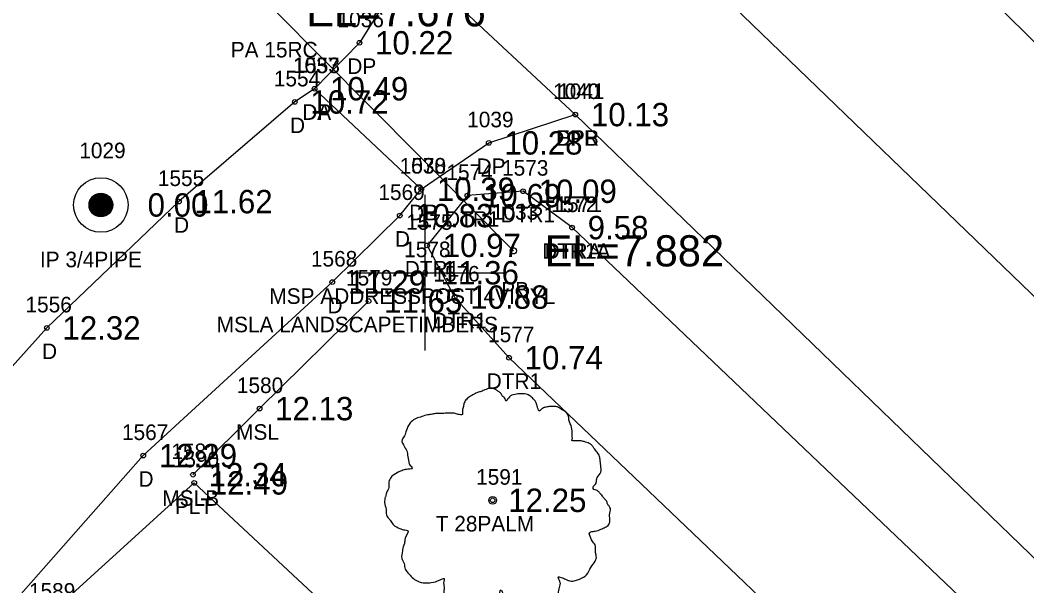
# Model space of a CAD drawing. Extents: x 2608598 to 2610682, y 641451 to 643526.
# Drawn here: x 2608785.1 to 2608849.7, y 643321 to 643357.3 of the extents above; entities that cross this region are included whole.
import ezdxf

# ---------------------------------------------------------------- set-up
doc = ezdxf.new("R2010")
doc.units = 0
for name, color, linetype in [('RD_EX_BldgApp', 7, 'Continuous'), ('RD_EX_BldgApp_txCode', 7, 'Continuous'), ('RD_EX_DR_Pipe', 7, 'Continuous'), ('RD_EX_DR_Pipe_txCode', 7, 'Continuous'), ('RD_EX_Driveway', 7, 'Continuous'), ('RD_EX_Driveway_txCode', 7, 'Continuous'), ('RD_EX_DV_Prop_txCode', 7, 'Continuous'), ('RD_EX_DV_PropPin', 7, 'Continuous'), ('RD_EX_H2O', 7, 'Continuous'), ('RD_EX_H2O_txCode', 7, 'Continuous'), ('RD_EX_Misc', 7, 'Continuous'), ('RD_EX_Misc_txCode', 7, 'Continuous'), ('RD_EX_Road', 7, 'Continuous'), ('RD_EX_Road_txCode', 7, 'Continuous'), ('RD_EX_TX_BldgApp_ELEV', 7, 'Continuous'), ('RD_EX_TX_Driveway_ELEV', 7, 'Continuous'), ('RD_EX_TX_DV_Prop_ELEV', 7, 'Continuous'), ('RD_EX_TX_H2O_ELEV', 7, 'Continuous'), ('RD_EX_TX_Misc_ELEV', 7, 'Continuous'), ('RD_EX_TX_Road_ELEV', 7, 'Continuous'), ('RD_EX_TX_VEG_ELEV', 7, 'Continuous'), ('RD_EX_VEG', 7, 'Continuous'), ('RD_EX_VEG_txCode', 7, 'Continuous'), ('RD_HC_Cl', 7, 'Continuous'), ('RD_SMD_Locator', 7, 'Continuous'), ('RD_TX_Pipe_ElevEX', 7, 'Continuous')]:
    doc.layers.add(name, color=color, linetype=linetype)

msp = doc.modelspace()

# ---------------------------------------------------------------- linework, layer by layer
at = {"layer": 'RD_EX_BldgApp'}
msp.add_lwpolyline([(2608782.007, 643313.14), (2608787.031, 643319.174), (2608796.295, 643327.605), (2608820.69, 643304.856), (2608835.733, 643299.436), (2608852.861, 643282.476), (2608829.792, 643260.004)], dxfattribs=at)
at = {"layer": 'RD_EX_DR_Pipe'}
msp.add_line((2608801.48, 643357.916), (2608816.779, 643342.503), dxfattribs=at)
at = {"layer": 'RD_EX_Driveway'}
for points in [[(2608810.184, 643361.1), (2608806.9, 643355.858), (2608804.015, 643352.911), (2608810.865, 643346.462), (2608815.199, 643349.433), (2608820.754, 643351.249)], [(2608804.015, 643352.911), (2608802.749, 643352.06), (2608795.306, 643345.662), (2608786.831, 643337.553), (2608778.8, 643328.638), (2608767.024, 643315.011), (2608761.179, 643303.915), (2608751.082, 643293.073)], [(2608763.886, 643279.174), (2608769.565, 643283.227), (2608776.886, 643278.867), (2608784.244, 643286.723), (2608773.721, 643299.147), (2608777.472, 643311.772), (2608793.023, 643329.358), (2608805.153, 643340.493), (2608809.483, 643344.767), (2608810.865, 643346.462)]]:
    msp.add_lwpolyline(points, dxfattribs=at)
at = {"layer": 'RD_EX_DV_PropPin'}
for p, q in [((2608790.265, 643344.687), (2608790.265, 643346.207)), ((2608790.3, 643344.686), (2608790.3, 643346.208)), ((2608790.335, 643344.687), (2608790.335, 643346.207)), ((2608789.565, 643345.251), (2608789.565, 643345.643)), ((2608789.6, 643345.149), (2608789.6, 643345.745)), ((2608789.635, 643345.078), (2608789.635, 643345.817)), ((2608789.67, 643345.021), (2608789.67, 643345.874)), ((2608789.705, 643344.973), (2608789.705, 643345.921)), ((2608789.74, 643344.932), (2608789.74, 643345.962)), ((2608789.775, 643344.896), (2608789.775, 643345.998)), ((2608789.81, 643344.865), (2608789.81, 643346.029)), ((2608789.845, 643344.837), (2608789.845, 643346.057)), ((2608789.88, 643344.813), (2608789.88, 643346.082)), ((2608789.915, 643344.791), (2608789.915, 643346.104)), ((2608789.95, 643344.772), (2608789.95, 643346.123)), ((2608789.985, 643344.754), (2608789.985, 643346.14)), ((2608790.02, 643344.74), (2608790.02, 643346.155)), ((2608790.055, 643344.727), (2608790.055, 643346.168)), ((2608790.09, 643344.716), (2608790.09, 643346.179)), ((2608790.125, 643344.707), (2608790.125, 643346.188)), ((2608790.16, 643344.699), (2608790.16, 643346.195)), ((2608790.195, 643344.693), (2608790.195, 643346.201)), ((2608790.23, 643344.689), (2608790.23, 643346.205)), ((2608790.37, 643344.689), (2608790.37, 643346.205)), ((2608790.405, 643344.693), (2608790.405, 643346.201)), ((2608790.44, 643344.699), (2608790.44, 643346.195)), ((2608790.475, 643344.707), (2608790.475, 643346.188)), ((2608790.51, 643344.716), (2608790.51, 643346.179)), ((2608790.545, 643344.727), (2608790.545, 643346.168)), ((2608790.58, 643344.74), (2608790.58, 643346.155)), ((2608790.615, 643344.754), (2608790.615, 643346.14)), ((2608790.65, 643344.772), (2608790.65, 643346.123)), ((2608790.685, 643344.791), (2608790.685, 643346.104)), ((2608790.72, 643344.813), (2608790.72, 643346.082)), ((2608790.755, 643344.837), (2608790.755, 643346.057)), ((2608790.79, 643344.865), (2608790.79, 643346.029)), ((2608790.825, 643344.896), (2608790.825, 643345.998)), ((2608790.86, 643344.932), (2608790.86, 643345.962)), ((2608790.895, 643344.973), (2608790.895, 643345.921)), ((2608790.93, 643345.021), (2608790.93, 643345.874)), ((2608790.965, 643345.078), (2608790.965, 643345.817)), ((2608791, 643345.149), (2608791, 643345.745)), ((2608791.035, 643345.251), (2608791.035, 643345.643))]:
    msp.add_line(p, q, dxfattribs=at)
for radius in [1.75, 0.761]:
    msp.add_circle((2608790.3, 643345.447), radius, dxfattribs=at)
at = {"layer": 'RD_EX_H2O'}
for points in [[(2608820.546, 643343.992), (2608817.399, 643346.329), (2608813.824, 643346.047), (2608811.242, 643342.853), (2608813.008, 643339.533), (2608816.498, 643335.639), (2608871.769, 643282.859), (2608887.42, 643272.574)], [(2608820.546, 643343.992), (2608878.381, 643288.901), (2608899.698, 643269.636), (2608901.301, 643266.137), (2608896.987, 643262.995), (2608887.42, 643272.574)]]:
    msp.add_lwpolyline(points, dxfattribs=at)
at = {"layer": 'RD_EX_Misc'}
for p, q in [((2608811.115, 643336.096), (2608811.115, 643346.096)), ((2608806.115, 643341.096), (2608816.115, 643341.096))]:
    msp.add_line(p, q, dxfattribs=at)
msp.add_lwpolyline([(2608807.48, 643339.273), (2608800.483, 643332.373), (2608796.213, 643328.133)], dxfattribs=at)
at = {"layer": 'RD_EX_Road'}
for points in [[(2608823.565, 643381.898), (2608829.584, 643376.805), (2608846.192, 643359.903), (2608852.068, 643354.1), (2608873.124, 643334.611), (2608877.912, 643330.135), (2608897.264, 643311.51), (2608898.769, 643309.298), (2608970.3, 643240.177), (2609042.495, 643170.94), (2609058.512, 643155.458)], [(2608806.889, 643364.989), (2608810.184, 643361.1), (2608820.754, 643351.249), (2608881.81, 643292.235), (2608917.833, 643257.495), (2608933.208, 643242.709), (2608954.068, 643222.833), (2609026.064, 643154.189), (2609039.601, 643139.963), (2609073.879, 643106.954), (2609100.48, 643081.888), (2609124.194, 643058.866), (2609171.612, 643013.711), (2609183.195, 643002.284), (2609197.913, 642988.365), (2609247.586, 642940.954), (2609328.02, 642863.599), (2609402.609, 642790.299), (2609474.235, 642720.69), (2609483.838, 642711.579), (2609495.782, 642699.917), (2609509.808, 642686.45)]]:
    msp.add_lwpolyline(points, dxfattribs=at)
at = {"layer": 'RD_EX_VEG'}
for centre, radius in [((2608815.448, 643326.487), 0.25), ((2608815.436, 643326.468), 0.0001)]:
    msp.add_circle(centre, radius, dxfattribs=at)
for points in [[(2608815.58, 643333.654), (2608815.28, 643333.679), (2608814.956, 643333.579), (2608814.706, 643333.479), (2608814.481, 643333.404), (2608814.256, 643333.304), (2608813.956, 643333.129), (2608813.731, 643332.929), (2608813.606, 643332.679), (2608813.556, 643332.454), (2608813.506, 643332.18), (2608813.506, 643332.005), (2608813.381, 643331.98), (2608813.231, 643332.005), (2608812.981, 643332.08), (2608812.731, 643332.08), (2608812.482, 643332.08), (2608812.132, 643332.055), (2608811.782, 643332.055), (2608811.507, 643332.005), (2608811.182, 643331.955), (2608810.807, 643331.83), (2608810.457, 643331.705), (2608810.158, 643331.455), (2608809.908, 643330.98), (2608809.783, 643330.63), (2608809.633, 643330.38), (2608809.783, 643329.931), (2608809.958, 643329.581), (2608809.983, 643329.381), (2608810.058, 643328.956), (2608810.158, 643328.731), (2608810.283, 643328.531), (2608810.208, 643328.506), (2608809.833, 643328.456), (2608809.533, 643328.356), (2608809.108, 643328.131), (2608808.883, 643327.906), (2608808.783, 643327.582), (2608808.758, 643327.232), (2608808.658, 643327.032), (2608808.583, 643326.757), (2608808.558, 643326.682), (2608808.508, 643326.357), (2608808.608, 643325.907), (2608808.633, 643325.557), (2608808.758, 643325.333), (2608808.908, 643325.158), (2608809.083, 643324.908), (2608809.483, 643324.683), (2608809.808, 643324.583), (2608810.008, 643324.558), (2608809.833, 643324.058), (2608809.783, 643323.708), (2608809.658, 643323.308), (2608809.658, 643323.234), (2608809.608, 643322.759), (2608809.758, 643322.434), (2608809.833, 643322.059), (2608810.008, 643321.834), (2608810.283, 643321.534), (2608810.607, 643321.309), (2608811.107, 643321.184), (2608811.507, 643321.209), (2608812.082, 643321.384), (2608812.332, 643321.459), (2608812.307, 643321.284), (2608812.332, 643320.909), (2608812.332, 643320.485), (2608812.482, 643320.16), (2608812.582, 643319.885), (2608812.731, 643319.635), (2608813.056, 643319.41), (2608813.456, 643319.335), (2608813.881, 643319.185), (2608814.331, 643319.11), (2608814.831, 643319.085), (2608815.43, 643319.235), (2608815.705, 643319.36), (2608815.805, 643319.535), (2608816.005, 643319.91), (2608815.955, 643320.135), (2608815.98, 643320.735), (2608816.08, 643320.56), (2608816.255, 643320.21), (2608816.755, 643319.91), (2608817.155, 643319.735), (2608817.629, 643319.585), (2608817.929, 643319.51), (2608818.404, 643319.585), (2608818.779, 643319.66), (2608819.154, 643319.785), (2608819.454, 643320.06), (2608819.628, 643320.335), (2608819.678, 643320.61), (2608819.753, 643320.984), (2608819.803, 643321.159)], [(2608819.803, 643321.159), (2608819.728, 643321.334), (2608819.678, 643321.584), (2608819.753, 643321.559), (2608819.928, 643321.509), (2608820.203, 643321.384), (2608820.428, 643321.309), (2608820.753, 643321.334), (2608821.028, 643321.434), (2608821.478, 643321.709), (2608821.753, 643322.184), (2608822.027, 643322.584), (2608822.102, 643322.909), (2608822.052, 643323.134), (2608822.027, 643323.633), (2608821.827, 643323.883), (2608821.777, 643324.008), (2608821.678, 643324.408), (2608821.753, 643324.458), (2608822.027, 643324.508), (2608822.402, 643324.633), (2608822.677, 643324.758), (2608822.902, 643324.933), (2608822.977, 643325.158), (2608822.952, 643325.557), (2608823.002, 643325.957), (2608822.927, 643326.107), (2608822.827, 643326.257), (2608822.752, 643326.457), (2608822.602, 643326.607), (2608822.502, 643326.757), (2608822.402, 643326.857), (2608822.277, 643327.007), (2608822.102, 643327.132), (2608821.952, 643327.182), (2608821.902, 643327.332), (2608822.052, 643327.532), (2608822.102, 643327.632), (2608822.127, 643327.856), (2608822.352, 643328.206), (2608822.402, 643328.606), (2608822.352, 643329.031), (2608822.302, 643329.306), (2608822.152, 643329.581), (2608821.952, 643329.831), (2608821.827, 643330.006), (2608821.653, 643330.13), (2608821.328, 643330.255), (2608821.078, 643330.305), (2608820.728, 643330.305), (2608820.528, 643330.355), (2608820.553, 643330.405), (2608820.553, 643330.555), (2608820.553, 643330.83), (2608820.478, 643331.28), (2608820.328, 643331.78), (2608820.328, 643331.805), (2608820.228, 643332.055), (2608820.003, 643332.255), (2608819.828, 643332.354), (2608819.628, 643332.479), (2608819.379, 643332.504), (2608819.079, 643332.504), (2608818.804, 643332.454), (2608818.604, 643332.354), (2608818.429, 643332.23), (2608818.354, 643332.379), (2608818.254, 643332.679), (2608818.204, 643332.829), (2608818.054, 643333.004), (2608817.829, 643333.204), (2608817.379, 643333.329), (2608816.755, 643333.254), (2608816.455, 643333.054), (2608816.305, 643332.879), (2608816.255, 643333.004), (2608816.055, 643333.204), (2608815.955, 643333.379), (2608815.78, 643333.504), (2608815.63, 643333.604), (2608815.53, 643333.654)]]:
    msp.add_spline(points, degree=3, dxfattribs=at)
at = {"layer": 'RD_HC_Cl'}
msp.add_line((2608814.812, 643373.733), (2610092.394, 642140.787), dxfattribs=at)
at = {"layer": 'RD_SMD_Locator'}
for centre, radius in [((2608806.9, 643355.858), 0.15), ((2608804.015, 643352.911), 0.15), ((2608804.015, 643352.911), 0.15), ((2608802.749, 643352.06), 0.15), ((2608820.754, 643351.249), 0.15), ((2608820.754, 643351.249), 0.15), ((2608815.199, 643349.433), 0.15), ((2608810.865, 643346.462), 0.15), ((2608810.865, 643346.462), 0.15), ((2608817.399, 643346.329), 0.15), ((2608790.3, 643345.447), 0.15), ((2608795.306, 643345.662), 0.15), ((2608813.824, 643346.047), 0.15), ((2608809.483, 643344.767), 0.15), ((2608820.546, 643343.992), 0.15), ((2608820.546, 643343.992), 0.15), ((2608811.242, 643342.853), 0.15), ((2608816.779, 643342.503), 0.2), ((2608811.115, 643341.096), 0.15), ((2608805.153, 643340.493), 0.15), ((2608807.48, 643339.273), 0.15), ((2608813.008, 643339.533), 0.15), ((2608786.831, 643337.553), 0.15), ((2608816.498, 643335.639), 0.15), ((2608800.483, 643332.373), 0.15), ((2608793.023, 643329.358), 0.15), ((2608796.213, 643328.133), 0.15), ((2608796.295, 643327.605), 0.15), ((2608815.448, 643326.487), 0.15)]:
    msp.add_circle(centre, radius, dxfattribs=at)

# ---------------------------------------------------------------- texts
at = {"layer": 'RD_EX_BldgApp_txCode'}
for s, p in [('1590', (2608794.909, 643328.605)), ('PLT', (2608795.051, 643325.605)), ('1589', (2608785.684, 643320.174))]:
    msp.add_text(s, height=1, dxfattribs=at).set_placement(p)
at = {"layer": 'RD_EX_DR_Pipe_txCode'}
for s, p in [('PA 15RC', (2608798.637, 643354.916)), ('1033', (2608815.393, 643344.503)), ('PB', (2608816, 643339.503))]:
    msp.add_text(s, height=1, dxfattribs=at).set_placement(p)
at = {"layer": 'RD_EX_Driveway_txCode'}
for s, p in [('1036', (2608805.491, 643356.858)), ('1037', (2608802.629, 643353.911)), ('1553', (2608802.668, 643353.911)), ('DP', (2608806.12, 643353.858)), ('1554', (2608801.402, 643353.06)), ('1040', (2608819.329, 643352.249)), ('DA', (2608803.219, 643350.911)), ('DP', (2608803.235, 643350.911)), ('1039', (2608813.813, 643350.433)), ('D', (2608802.441, 643350.06)), ('DPB', (2608819.503, 643349.249)), ('1038', (2608809.48, 643347.462)), ('1570', (2608809.48, 643347.462)), ('DP', (2608814.419, 643347.433)), ('1555', (2608793.959, 643346.662)), ('1569', (2608808.113, 643345.767)), ('DP', (2608810.086, 643344.462)), ('DB', (2608810.086, 643344.462)), ('D', (2608794.999, 643343.662)), ('D', (2608809.176, 643342.767)), ('1568', (2608803.783, 643341.493)), ('1556', (2608785.461, 643338.553)), ('D', (2608804.846, 643338.493)), ('D', (2608786.524, 643335.553)), ('1567', (2608791.653, 643330.358)), ('D', (2608792.716, 643327.358))]:
    msp.add_text(s, height=1, dxfattribs=at).set_placement(p)
at = {"layer": 'RD_EX_DV_Prop_txCode'}
for s, p in [('1029', (2608788.914, 643348.447)), ('IP 3/4PIPE', (2608786.39, 643341.447))]:
    msp.add_text(s, height=1, dxfattribs=at).set_placement(p)
at = {"layer": 'RD_EX_H2O_txCode'}
for s, p in [('1573', (2608816.052, 643347.329)), ('1574', (2608812.478, 643347.047)), ('1572', (2608819.2, 643344.992)), ('1571', (2608819.483, 643344.992)), ('DTR1', (2608812.391, 643344.047)), ('DTR1', (2608815.966, 643344.329)), ('1575', (2608809.896, 643343.853)), ('DTR1A', (2608818.625, 643341.992)), ('DTRA', (2608818.79, 643341.992)), ('DTR1', (2608809.809, 643340.853)), ('1576', (2608811.638, 643340.533)), ('DTR1', (2608811.575, 643337.533)), ('1577', (2608815.152, 643336.639)), ('DTR1', (2608815.065, 643333.639))]:
    msp.add_text(s, height=1, dxfattribs=at).set_placement(p)
at = {"layer": 'RD_EX_Misc_txCode'}
for s, p in [('1578', (2608809.769, 643342.096)), ('1579', (2608806.033, 643340.273)), ('MSP ADDRESSPOST 4VINYL', (2608801.115, 643339.096)), ('MSLA LANDSCAPETIMBERS', (2608797.735, 643337.273)), ('1580', (2608799.031, 643333.373)), ('MSL', (2608798.98, 643330.373)), ('1581', (2608794.826, 643329.133)), ('MSLB', (2608794.242, 643326.133))]:
    msp.add_text(s, height=1, dxfattribs=at).set_placement(p)
at = {"layer": 'RD_EX_Road_txCode'}
for s, p in [('1041', (2608819.652, 643352.249)), ('EPR', (2608819.526, 643349.249))]:
    msp.add_text(s, height=1, dxfattribs=at).set_placement(p)
at = {"layer": 'RD_EX_TX_BldgApp_ELEV'}
msp.add_text('12.49', height=1.5, dxfattribs=at).set_placement((2608797.295, 643326.855))
at = {"layer": 'RD_EX_TX_Driveway_ELEV'}
for s, p in [('10.22', (2608807.9, 643355.108)), ('10.49', (2608805.015, 643352.161)), ('10.49', (2608805.015, 643352.161)), ('10.72', (2608803.749, 643351.31)), ('10.13', (2608821.754, 643350.499)), ('10.28', (2608816.199, 643348.683)), ('10.39', (2608811.865, 643345.712)), ('10.39', (2608811.865, 643345.712)), ('11.62', (2608796.306, 643344.912)), ('10.83', (2608810.483, 643344.017)), ('11.29', (2608806.153, 643339.743)), ('12.32', (2608787.831, 643336.803)), ('12.29', (2608794.023, 643328.608))]:
    msp.add_text(s, height=1.5, dxfattribs=at).set_placement(p)
at = {"layer": 'RD_EX_TX_DV_Prop_ELEV'}
msp.add_text('0.00', height=1.5, dxfattribs=at).set_placement((2608793.3, 643344.697))
at = {"layer": 'RD_EX_TX_H2O_ELEV'}
for s, p in [('10.09', (2608818.399, 643345.579)), ('10.69', (2608814.824, 643345.297)), ('9.58', (2608821.546, 643343.242)), ('9.58', (2608821.546, 643343.242)), ('10.97', (2608812.242, 643342.103)), ('10.88', (2608814.008, 643338.783)), ('10.74', (2608817.498, 643334.889))]:
    msp.add_text(s, height=1.5, dxfattribs=at).set_placement(p)
at = {"layer": 'RD_EX_TX_Misc_ELEV'}
for s, p in [('11.36', (2608812.115, 643340.346)), ('11.65', (2608808.48, 643338.523)), ('12.13', (2608801.483, 643331.623)), ('12.34', (2608797.213, 643327.383))]:
    msp.add_text(s, height=1.5, dxfattribs=at).set_placement(p)
at = {"layer": 'RD_EX_TX_Road_ELEV'}
msp.add_text('10.13', height=1.5, dxfattribs=at).set_placement((2608821.754, 643350.499))
at = {"layer": 'RD_EX_TX_VEG_ELEV'}
msp.add_text('12.25', height=1.5, dxfattribs=at).set_placement((2608816.448, 643325.737))
at = {"layer": 'RD_EX_VEG_txCode'}
for s, p in [('1591', (2608814.385, 643327.487)), ('T 28PALM', (2608811.795, 643324.487))]:
    msp.add_text(s, height=1, dxfattribs=at).set_placement(p)
at = {"layer": 'RD_TX_Pipe_ElevEX'}
for s, p in [('EL=7.676', (2608803.48, 643356.916)), ('EL=7.882', (2608818.779, 643341.503))]:
    msp.add_text(s, height=2, dxfattribs=at).set_placement(p)

doc.saveas('drawing.dxf')
